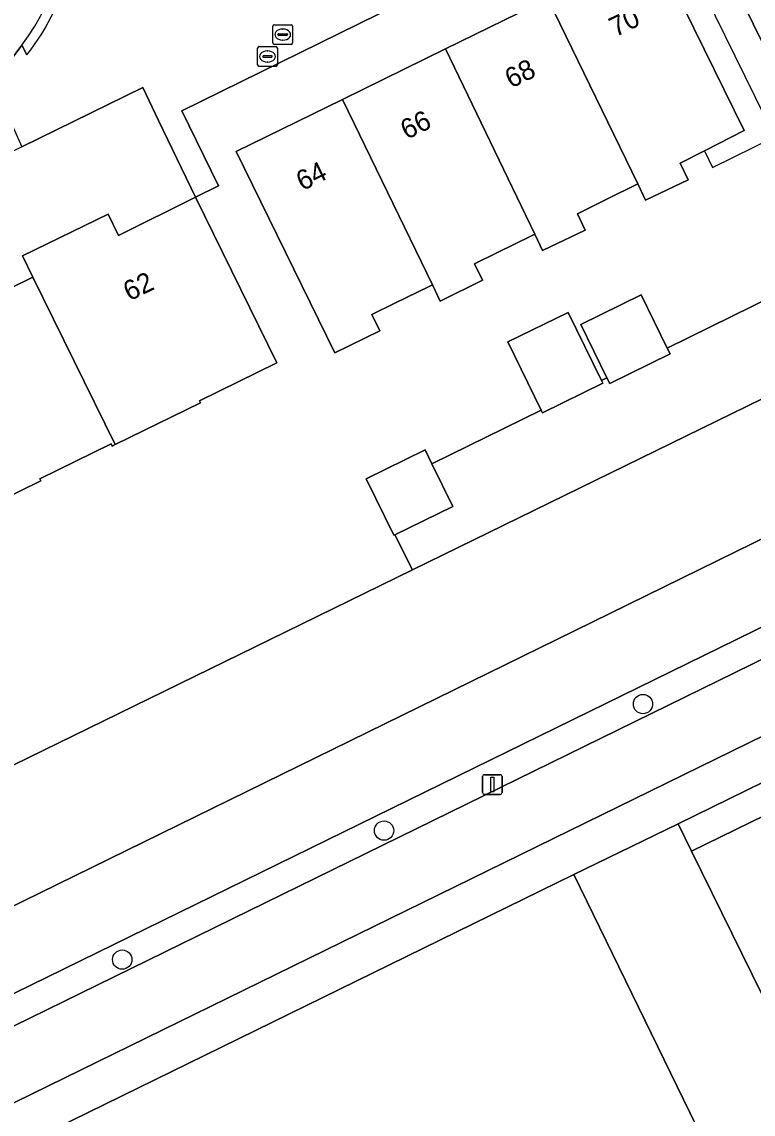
# Model space of a CAD drawing. Extents: x 160455 to 162082, y 388339 to 389736.
# Drawn here: x 160929.1 to 160966.2, y 388725.9 to 388781.3 of the extents above; entities that cross this region are included whole.
import ezdxf

# ---------------------------------------------------------------- set-up
doc = ezdxf.new("R2010")
doc.units = 0
for name, color, linetype in [('IMGEO_Boom', 7, 'Continuous'), ('IMGEO_Erf', 7, 'Continuous'), ('IMGEO_Fietspad_gesloten', 7, 'Continuous'), ('IMGEO_Groenvoorziening', 7, 'Continuous'), ('IMGEO_Haag', 7, 'Continuous'), ('IMGEO_Lichtmast', 7, 'Continuous'), ('IMGEO_Oever', 7, 'Continuous'), ('IMGEO_Pand', 7, 'Continuous'), ('IMGEO_Pand_nummerreeks', 7, 'Continuous'), ('IMGEO_Pand_overbouw', 7, 'Continuous'), ('IMGEO_Parkeervlak_open', 7, 'Continuous'), ('IMGEO_Rijbaan_lokaal_gesloten', 7, 'Continuous'), ('IMGEO_Rijbaan_lokaal_open', 7, 'Continuous'), ('IMGEO_Rioolput', 7, 'Continuous'), ('IMGEO_Voetpad_open', 7, 'Continuous'), ('IMGEO_Waterloop', 7, 'Continuous')]:
    doc.layers.add(name, color=color, linetype=linetype)

msp = doc.modelspace()

# ---------------------------------------------------------------- linework, layer by layer
at = {"layer": 'IMGEO_Boom'}
for centre in [(160960.603, 388746.726), (160947.478, 388740.315), (160934.206, 388733.778)]:
    msp.add_circle(centre, 0.489, dxfattribs=at)
at = {"layer": 'IMGEO_Erf'}
for points in [[(160966.804, 388779.925), (160962.46, 388788.776), (160962.186, 388789.06), (160937.225, 388776.774), (160939.088, 388772.99), (160937.925, 388772.412)], [(160961.144, 388785.109), (160965.734, 388775.78), (160963.716, 388774.751), (160962.484, 388774.122), (160962.886, 388773.294), (160960.737, 388772.251), (160960.335, 388773.079), (160960.167, 388772.996), (160958.912, 388772.376), (160958.438, 388772.141), (160957.284, 388771.57), (160957.68, 388770.739), (160955.517, 388769.707), (160955.118, 388770.534), (160954.951, 388770.452), (160953.229, 388769.605), (160952.056, 388769.029), (160952.466, 388768.206), (160950.33, 388767.144), (160949.928, 388767.97), (160949.758, 388767.887), (160948.616, 388767.329), (160948.028, 388767.041), (160946.863, 388766.471), (160947.265, 388765.638), (160944.985, 388764.514), (160939.988, 388774.718), (160945.366, 388777.36), (160950.593, 388779.927), (160955.774, 388782.471)], [(160937.925, 388772.412), (160936.05, 388776.299), (160935.249, 388777.96), (160929.117, 388774.962), (160878.066, 388750), (160811.085, 388717.249)], [(160927.736, 388767.405), (160929.539, 388768.286), (160929.681, 388768.355), (160929.152, 388769.432), (160933.494, 388771.552), (160934.015, 388770.47), (160937.925, 388772.412), (160942.041, 388764.012), (160938.116, 388762.094), (160938.169, 388761.986), (160933.848, 388759.874), (160933.696, 388759.8), (160933.644, 388759.908), (160930.024, 388758.139), (160930.077, 388758.031), (160925.745, 388755.914)], [(160766.298, 388664.267), (160941.708, 388750), (160948.921, 388753.525), (160948.021, 388755.303), (160947.977, 388755.282), (160946.576, 388758.143), (160949.559, 388759.604), (160949.905, 388758.897), (160955.447, 388761.62), (160953.756, 388765.074), (160956.812, 388766.571), (160958.502, 388763.122), (160958.774, 388763.255), (160957.453, 388765.953), (160960.515, 388767.453), (160961.835, 388764.759), (160968.352, 388767.962)]]:
    msp.add_lwpolyline(points, dxfattribs=at)
msp.add_lwpolyline([(161020.621, 388731.678), (161006.266, 388761.054), (161005.821, 388761.965), (161000, 388759.109), (160981.436, 388750), (160962.382, 388740.651), (160963.059, 388739.275), (160967.518, 388741.446), (160982.232, 388711.367), (160983.598, 388711.346), (160986.381, 388705.418), (161000, 388705.227), (161020.646, 388704.937), (161020.64, 388710.846), (161020.64, 388711.063)], close=True, dxfattribs=at)
at = {"layer": 'IMGEO_Fietspad_gesloten'}
for points in [[(160976.671, 388750), (161000, 388761.421), (161006.396, 388764.552), (161005.803, 388768.175), (161001.6, 388766.116), (161000, 388765.333), (160968.696, 388750), (160830.802, 388682.457), (160825.311, 388679.157), (160825.396, 388678.948)], [(160835.236, 388680.785), (160877.263, 388701.324), (160886.716, 388705.962), (160976.671, 388750)]]:
    msp.add_lwpolyline(points, dxfattribs=at)
at = {"layer": 'IMGEO_Groenvoorziening'}
for points in [[(160985.165, 388771.24), (160998.756, 388778.042), (160998.487, 388778.589), (160984.612, 388771.79), (160982.973, 388775.146), (160971.723, 388769.618), (160971.437, 388769.478), (160971.525, 388769.298), (160968.438, 388767.786), (160968.352, 388767.962), (160961.835, 388764.759), (160961.98, 388764.463), (160958.917, 388762.963), (160958.774, 388763.255), (160958.502, 388763.122), (160958.569, 388762.984), (160955.512, 388761.487), (160955.447, 388761.62), (160949.905, 388758.897), (160950.96, 388756.743), (160948.021, 388755.303), (160948.921, 388753.525)], [(160968.696, 388750), (161000, 388765.333), (161001.6, 388766.116), (161001.239, 388766.89), (161000.979, 388767.447), (160965.347, 388750), (160778.313, 388658.421), (160776.807, 388656.846), (160777.453, 388655.571), (160825.396, 388678.948), (160825.311, 388679.157), (160830.802, 388682.457)]]:
    msp.add_lwpolyline(points, close=True, dxfattribs=at)
msp.add_lwpolyline([(160972.792, 388705.905), (160957.1, 388738.085), (160888.295, 388704.396)], dxfattribs=at)
at = {"layer": 'IMGEO_Haag'}
msp.add_lwpolyline([(160968.696, 388750), (161000, 388765.333), (161001.6, 388766.116), (161001.239, 388766.89), (161000.979, 388767.447), (160965.347, 388750), (160778.313, 388658.421), (160776.807, 388656.846), (160777.453, 388655.571), (160825.396, 388678.948), (160825.311, 388679.157), (160830.802, 388682.457)], close=True, dxfattribs=at)
at = {"layer": 'IMGEO_Lichtmast'}
for p, q in [((160952.57, 388743.148), (160953.36, 388743.148)), ((160953.36, 388743.148), (160952.57, 388743.148)), ((160952.47, 388742.248), (160952.47, 388743.048)), ((160952.47, 388743.048), (160952.47, 388742.248)), ((160953.46, 388743.048), (160953.46, 388742.248)), ((160953.46, 388742.248), (160953.46, 388743.048)), ((160953.36, 388742.148), (160952.57, 388742.148)), ((160952.57, 388742.148), (160953.36, 388742.148))]:
    msp.add_line(p, q, dxfattribs=at)
msp.add_lwpolyline([(160952.89, 388743.023), (160953.04, 388743.023), (160953.04, 388742.273), (160952.89, 388742.273), (160952.89, 388743.023)], dxfattribs=at)
for centre, start, end in [((160952.57, 388743.048), 90, 180), ((160952.57, 388743.048), 90, 180), ((160953.36, 388743.048), 0, 90), ((160953.36, 388743.048), 360, 90), ((160952.57, 388742.248), 180, 270), ((160952.57, 388742.248), 180, 270), ((160953.36, 388742.248), 270, 0), ((160953.36, 388742.248), 270, 0)]:
    msp.add_arc(centre, 0.1, start, end, dxfattribs=at)
at = {"layer": 'IMGEO_Oever'}
msp.add_lwpolyline([(160965.347, 388750), (161000.979, 388767.447), (161004.923, 388771.881), (161004.47, 388772.822), (161004.366, 388772.775), (161004.045, 388773.679), (161000, 388771.638), (160986.989, 388765.073), (160956.23, 388750), (160783.435, 388665.323), (160769.08, 388658.493), (160770.196, 388656.176), (160776.807, 388656.846), (160778.313, 388658.421)], close=True, dxfattribs=at)
at = {"layer": 'IMGEO_Pand'}
for points in [[(160961.144, 388785.109), (160955.774, 388782.471), (160960.335, 388773.079), (160960.737, 388772.251), (160962.886, 388773.294), (160962.484, 388774.122), (160963.716, 388774.751), (160965.734, 388775.78)], [(160955.774, 388782.471), (160950.593, 388779.927), (160955.118, 388770.534), (160955.517, 388769.707), (160957.68, 388770.739), (160957.284, 388771.57), (160958.438, 388772.141), (160958.912, 388772.376), (160960.167, 388772.996), (160960.335, 388773.079)], [(160950.593, 388779.927), (160945.366, 388777.36), (160949.928, 388767.97), (160950.33, 388767.144), (160952.466, 388768.206), (160952.056, 388769.029), (160953.229, 388769.605), (160954.951, 388770.452), (160955.118, 388770.534)], [(160945.366, 388777.36), (160939.988, 388774.718), (160944.985, 388764.514), (160947.265, 388765.638), (160946.863, 388766.471), (160948.028, 388767.041), (160948.616, 388767.329), (160949.758, 388767.887), (160949.928, 388767.97)], [(160937.925, 388772.412), (160934.015, 388770.47), (160933.494, 388771.552), (160929.152, 388769.432), (160929.681, 388768.355), (160933.848, 388759.874), (160938.169, 388761.986), (160938.116, 388762.094), (160942.041, 388764.012)], [(160929.681, 388768.355), (160929.539, 388768.286), (160927.736, 388767.405), (160925.932, 388766.523), (160925.406, 388767.601), (160921.07, 388765.485), (160921.596, 388764.407), (160925.745, 388755.914), (160930.077, 388758.031), (160930.024, 388758.139), (160933.644, 388759.908), (160933.696, 388759.8), (160933.848, 388759.874)], [(160961.835, 388764.759), (160960.515, 388767.453), (160957.453, 388765.953), (160958.774, 388763.255), (160958.917, 388762.963), (160961.98, 388764.463)], [(160955.447, 388761.62), (160955.512, 388761.487), (160958.569, 388762.984), (160958.502, 388763.122), (160956.812, 388766.571), (160953.756, 388765.074)], [(160949.905, 388758.897), (160949.559, 388759.604), (160946.576, 388758.143), (160947.977, 388755.282), (160948.021, 388755.303), (160950.96, 388756.743)]]:
    msp.add_lwpolyline(points, close=True, dxfattribs=at)
at = {"layer": 'IMGEO_Pand_overbouw'}
msp.add_lwpolyline([(160961.144, 388785.109), (160965.734, 388775.78), (160963.716, 388774.751), (160964.12, 388773.919), (160967.282, 388775.466), (160962.275, 388785.678)], close=True, dxfattribs=at)
at = {"layer": 'IMGEO_Parkeervlak_open'}
for points in [[(160948.872, 388833.674), (160944.14, 388831.355), (160962.609, 388793.497), (160962.686, 388793.342), (160964.475, 388789.746), (160962.46, 388788.776), (160966.804, 388779.925), (160971.277, 388770.846), (160975.724, 388773.041), (160967.282, 388790.15), (160969.637, 388791.303)], [(160982.232, 388711.367), (160967.518, 388741.446), (160963.059, 388739.275), (160968.684, 388727.84), (160972.373, 388720.249), (160976.723, 388711.453)]]:
    msp.add_lwpolyline(points, close=True, dxfattribs=at)
at = {"layer": 'IMGEO_Rijbaan_lokaal_gesloten'}
msp.add_lwpolyline([(160923.089, 388781.332), (160922.221, 388780.848), (160922.077, 388780.78), (160918.996, 388779.324), (160899.56, 388769.847), (160880.511, 388760.545), (160877.968, 388759.28), (160879.999, 388755.357), (160881.617, 388756.126), (160901.535, 388765.865), (160926.684, 388778.165), (160927.363, 388778.614), (160928.626, 388779.448), (160929.119, 388780.101)], dxfattribs=at)
msp.add_arc((160919.69, 388787.169), 11.784, 323.1444, 8.1827, dxfattribs=at)
at = {"layer": 'IMGEO_Rijbaan_lokaal_open'}
msp.add_lwpolyline([(160963.059, 388739.275), (160962.382, 388740.651), (160957.1, 388738.085), (160972.792, 388705.905), (160972.937, 388705.607), (160977.941, 388705.537), (160986.381, 388705.418), (160983.598, 388711.346), (160982.232, 388711.367), (160976.723, 388711.453), (160972.373, 388720.249), (160968.684, 388727.84)], close=True, dxfattribs=at)
at = {"layer": 'IMGEO_Rioolput'}
for p, q in [((160941.842, 388780.22), (160941.842, 388781.072)), ((160941.917, 388781.146), (160942.769, 388781.146)), ((160942.33, 388780.926), (160942.355, 388780.926)), ((160942.843, 388781.072), (160942.843, 388780.22)), ((160942.101, 388780.64), (160942.101, 388780.652)), ((160942.539, 388780.603), (160942.141, 388780.603)), ((160942.144, 388780.689), (160942.542, 388780.689)), ((160942.353, 388780.366), (160942.328, 388780.366)), ((160942.585, 388780.652), (160942.585, 388780.64)), ((160941.071, 388779.108), (160941.071, 388779.96)), ((160941.146, 388780.034), (160941.998, 388780.034)), ((160941.559, 388779.814), (160941.584, 388779.814)), ((160942.769, 388780.146), (160941.917, 388780.146)), ((160942.072, 388779.96), (160942.072, 388779.108)), ((160941.33, 388779.528), (160941.33, 388779.54)), ((160941.768, 388779.491), (160941.37, 388779.491)), ((160941.373, 388779.577), (160941.771, 388779.577)), ((160941.582, 388779.254), (160941.557, 388779.254)), ((160941.814, 388779.54), (160941.814, 388779.528)), ((160941.998, 388779.034), (160941.146, 388779.034))]:
    msp.add_line(p, q, dxfattribs=at)
for points in [[(160941.842, 388780.22), (160941.842, 388781.072)], [(160941.917, 388781.146), (160942.769, 388781.146)], [(160942.843, 388781.072), (160942.843, 388780.22)], [(160941.071, 388779.108), (160941.071, 388779.96)], [(160941.146, 388780.034), (160941.998, 388780.034)], [(160942.769, 388780.146), (160941.917, 388780.146)], [(160942.072, 388779.96), (160942.072, 388779.108)], [(160941.998, 388779.034), (160941.146, 388779.034)]]:
    msp.add_lwpolyline(points, dxfattribs=at)
for centre, radius, start, end in [((160941.919, 388781.07), 0.0765, 91.552, 178.448), ((160941.919, 388781.07), 0.0765, 91.552, 178.448), ((160942.767, 388781.07), 0.0765, 1.552, 88.448), ((160942.767, 388781.07), 0.0765, 1.552, 88.448), ((160942.141, 388780.649), 0.0403, 85.8775, 175.7526), ((160942.138, 388780.639), 0.0366, 178.938, 274.7102), ((160942.542, 388780.646), 0.043, 264.8664, 352.4533), ((160942.546, 388780.651), 0.0386, 1.7309, 96.639), ((160941.148, 388779.958), 0.0765, 91.552, 178.448), ((160941.148, 388779.958), 0.0765, 91.552, 178.448), ((160941.919, 388780.222), 0.0765, 181.552, 268.448), ((160941.919, 388780.222), 0.0765, 181.552, 268.448), ((160941.996, 388779.958), 0.0765, 1.552, 88.448), ((160941.996, 388779.958), 0.0765, 1.552, 88.448), ((160942.767, 388780.222), 0.0765, 271.552, 358.448), ((160942.767, 388780.222), 0.0765, 271.552, 358.448), ((160941.37, 388779.537), 0.0403, 85.8775, 175.7526), ((160941.367, 388779.527), 0.0366, 178.938, 274.7102), ((160941.771, 388779.534), 0.043, 264.8664, 352.4533), ((160941.775, 388779.539), 0.0386, 1.7309, 96.639), ((160941.148, 388779.11), 0.0765, 181.552, 268.448), ((160941.148, 388779.11), 0.0765, 181.552, 268.448), ((160941.996, 388779.11), 0.0765, 271.552, 358.448), ((160941.996, 388779.11), 0.0765, 271.552, 358.448)]:
    msp.add_arc(centre, radius, start, end, dxfattribs=at)
for centre, major_axis, ratio, start_param, end_param in [((160942.329, 388780.646), (-0.387, 0.002), 0.722429, 4.712389, 7.853982), ((160942.354, 388780.646), (-0.39, 0.002), 0.717154, 1.570796, 4.712389), ((160941.558, 388779.534), (-0.387, 0.002), 0.722429, 4.712389, 7.853982), ((160941.583, 388779.534), (-0.39, 0.002), 0.717154, 1.570796, 4.712389)]:
    msp.add_ellipse(centre, major_axis=major_axis, ratio=ratio, start_param=start_param, end_param=end_param, dxfattribs=at)
at = {"layer": 'IMGEO_Voetpad_open'}
for points in [[(160929.375, 388779.613), (160929.119, 388780.101), (160928.626, 388779.448), (160928.178, 388778.717), (160927.831, 388777.792), (160929.117, 388774.962), (160935.249, 388777.96), (160936.05, 388776.299), (160937.925, 388772.412), (160939.088, 388772.99), (160937.225, 388776.774), (160962.186, 388789.06)], [(160929.119, 388780.101), (160929.375, 388779.613)], [(160957.1, 388738.085), (160962.382, 388740.651), (160981.436, 388750), (161000, 388759.109), (161005.821, 388761.965), (161007.303, 388762.692), (161006.396, 388764.552), (161000, 388761.421), (160976.671, 388750), (160886.716, 388705.962)], [(160888.295, 388704.396), (160957.1, 388738.085)]]:
    msp.add_lwpolyline(points, dxfattribs=at)
for centre, radius, start, end in [((160919.691, 388787.168), 12.282, 322.0396, 10.5978), ((160919.691, 388787.168), 12.282, 322.0396, 10.5978), ((160919.69, 388787.169), 11.784, 323.1444, 8.1827)]:
    msp.add_arc(centre, radius, start, end, dxfattribs=at)
at = {"layer": 'IMGEO_Waterloop'}
msp.add_lwpolyline([(160956.23, 388750), (160986.989, 388765.073), (161000, 388771.638), (161004.045, 388773.679), (161001.348, 388779.301), (161000, 388778.665), (160998.756, 388778.042), (160985.165, 388771.24), (160948.921, 388753.525), (160941.708, 388750), (160766.298, 388664.267), (160769.08, 388658.493), (160783.435, 388665.323)], close=True, dxfattribs=at)

# ---------------------------------------------------------------- texts
at = {"layer": 'IMGEO_Pand_nummerreeks'}
for s, rotation, p in [('70', 26.1613, (160959.206, 388780.503)), ('68', 26.1613, (160953.917, 388777.905)), ('66', 26.1613, (160948.625, 388775.307)), ('64', 26.1613, (160943.336, 388772.709)), ('62', 26.0696, (160934.572, 388767.121))]:
    msp.add_text(s, height=1, rotation=rotation, dxfattribs=at).set_placement(p)

doc.saveas('drawing.dxf')
